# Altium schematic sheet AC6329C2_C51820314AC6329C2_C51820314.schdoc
size 127 x 101 mm
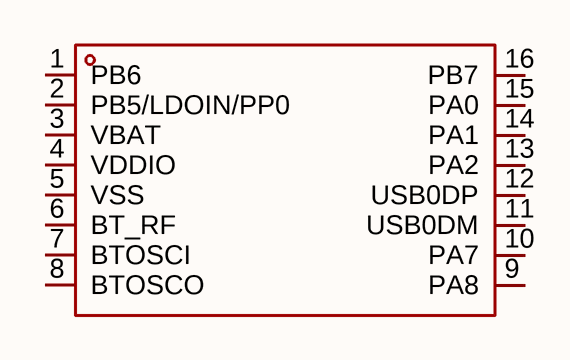
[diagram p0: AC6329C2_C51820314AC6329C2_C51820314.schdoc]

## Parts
U?  ac6329c2_c51820314  [SOP-16_L9.9-W3.9-P1.27-LS6.0-BL]  (value not drawn)

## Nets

Not connected (* = marked no-connect by the designer): U? 1(PB6) 2(PB5/LDOIN/PP0) 3(VBAT) 4(VDDIO) 5(VSS) 6(BT_RF) 7(BTOSCI) 8(BTOSCO) 9(PA8) 10(PA7) 11(USB0DM) 12(USB0DP) 13(PA2) 14(PA1) 15(PA0) 16(PB7)

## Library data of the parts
U? = ac6329c2_c51820314: CPU内核:RISC;CPU最大主频:96MHz;CPU位数:32 Bit;; Manufacturer: JL(杰理); AddInBom: yes; ModelId: ed96d47c1e844792b3e705d722a1a1fa; ModelTransform: 389.763,236.22,0,0,0,0,0,0,0; CPU Core: RISC; CPU Maximum Speed: 96MHz; Core Size: 32 Bit; Number of I/O: 10; Voltage - Supply: 1.8V~4.5V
